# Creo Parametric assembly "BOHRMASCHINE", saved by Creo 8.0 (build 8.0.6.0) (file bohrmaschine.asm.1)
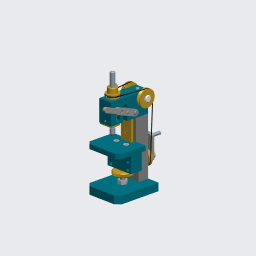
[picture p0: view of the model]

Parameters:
  ERSTELLER = "ARINDA"
  BENENNUNG = "Bohrmaschine"
  TEILETYP = "K"

Other parameters: MASSE, ROTATION1_STATIC_FRICTION, ROTATION1_KINETIC_FRICTION, ROTATION1_CONTACT_RADIUS, ROTATION1_RESTITUTION, ROTATION1_MINIMUM_LIMIT, ROTATION1_MAXIMUM_LIMIT, ROTATION1_ZERO_POSITION, TRANSLATION1_STATIC_FRICTION, TRANSLATION1_KINETIC_FRICTION, TRANSLATION1_RESTITUTION, TRANSLATION1_MINIMUM_LIMIT, TRANSLATION1_MAXIMUM_LIMIT, TRANSLATION1_ZERO_POSITION

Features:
  1. coordinate system
  2. datum plane "A_RECHTS_Y-Z"
  3. datum plane "A_OBEN_X-Z"
  4. datum plane "A_VORNE_X-Y"
  5. datum axis
  6. datum axis
  7. datum axis
  8. datum point "APNT0"
  9. component
  10. component
  11. component
  12. component
  13. component
  14. component
  15. component "GETRIEBEGEHÄUSE.ASM"
  16. component
  17. component
  18. component
  19. component
  20. component "RIEMEN.PRT"
  21. component
  22. component
  23. component
  24. component
  25. component
  26. component
  27. component
  28. component
  29. component
  30. component
  31. component

Other named items: KURBEL, AA_X, AA_Y, AA_Z, ACS0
